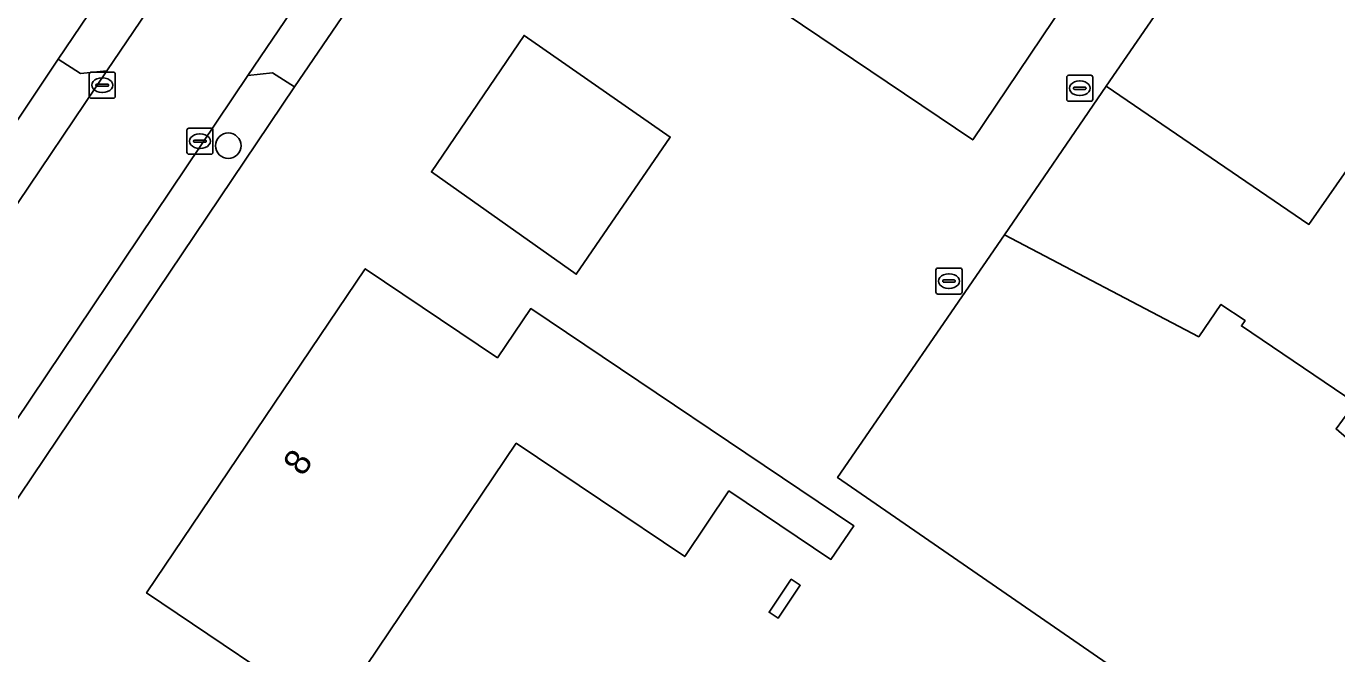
# Model space of a CAD drawing. Extents: x 163859 to 164644, y 379566 to 382155.
# Drawn here: x 164174.8 to 164225.1, y 381807.4 to 381831.6 of the extents above; entities that cross this region are included whole.
import ezdxf

# ---------------------------------------------------------------- set-up
doc = ezdxf.new("R2010")
doc.units = 0
for name, color, linetype in [('IMGEO_Boom', 7, 'Continuous'), ('IMGEO_Erf', 7, 'Continuous'), ('IMGEO_Kolk', 7, 'Continuous'), ('IMGEO_Muur', 7, 'Continuous'), ('IMGEO_Pand', 7, 'Continuous'), ('IMGEO_Pand_nummerreeks', 7, 'Continuous'), ('IMGEO_Rijbaan_lokaal_open', 7, 'Continuous'), ('IMGEO_Voetpad_halfverhard', 7, 'Continuous')]:
    doc.layers.add(name, color=color, linetype=linetype)

msp = doc.modelspace()

# ---------------------------------------------------------------- linework, layer by layer
at = {"layer": 'IMGEO_Boom'}
msp.add_circle((164182.545, 381826.968), 0.489, dxfattribs=at)
at = {"layer": 'IMGEO_Erf'}
for points in [[(164172.905, 381825.67), (164176.013, 381830.292), (164180.059, 381836.297), (164181.855, 381838.961), (164183.999, 381842.144), (164184.705, 381843.191), (164191.306, 381852.987), (164191.32, 381853.008), (164191.58, 381853.421), (164189.365, 381854.902), (164179.829, 381861.277), (164174.878, 381856.933)], [(164235.043, 381794.138), (164205.955, 381814.209), (164212.364, 381823.54), (164216.274, 381829.253), (164219.843, 381834.466), (164216.141, 381836.213), (164213.566, 381838.056), (164211.492, 381839.541), (164211.311, 381839.272), (164210.023, 381840.13), (164210.234, 381840.441), (164208.977, 381841.341), (164200.437, 381847.454), (164198.212, 381849.047), (164197.859, 381848.521), (164188.424, 381834.578), (164188.626, 381834.431), (164188.179, 381833.768), (164185.088, 381829.228), (164165.885, 381800.687)], [(164287.783, 381790.232), (164256.006, 381812.389), (164255.882, 381812.656), (164254.893, 381811.01), (164254.142, 381811.525), (164232.273, 381826.526), (164232.842, 381827.338), (164225.998, 381831.919), (164222.08, 381834.543), (164222.298, 381834.862), (164220.66, 381835.65), (164219.843, 381834.466), (164216.274, 381829.253), (164224.066, 381823.939), (164225.891, 381826.571), (164230.279, 381823.603), (164230.417, 381823.852)], [(164232.439, 381822.106), (164231.909, 381821.33), (164235.808, 381818.657), (164230.696, 381811.217), (164225.107, 381816.082), (164225.837, 381817.086), (164221.471, 381820.037), (164221.61, 381820.246), (164220.683, 381820.865), (164219.83, 381819.623), (164212.364, 381823.54), (164205.955, 381814.209), (164235.043, 381794.138), (164235.285, 381793.932), (164235.601, 381793.483), (164234.237, 381791.715), (164240.69, 381784.76), (164245.37, 381788.308), (164248.754, 381793.758), (164252.441, 381799.696), (164251.999, 381799.981), (164253.852, 381802.608)]]:
    msp.add_lwpolyline(points, dxfattribs=at)
for points in [[(164197.39, 381836.467), (164201.794, 381843.035), (164208.819, 381838.297), (164215.56, 381833.752), (164211.149, 381827.193)], [(164190.351, 381825.963), (164193.911, 381831.206), (164199.528, 381827.3), (164195.916, 381822.029)], [(164179.403, 381809.776), (164187.804, 381822.239), (164192.882, 381818.816), (164194.165, 381820.708), (164206.574, 381812.36), (164205.701, 381811.062), (164201.779, 381813.699), (164200.08, 381811.174), (164193.606, 381815.529), (164186.515, 381804.988)], [(164204.176, 381810.303), (164204.52, 381810.071), (164203.666, 381808.802), (164203.322, 381809.033)]]:
    msp.add_lwpolyline(points, close=True, dxfattribs=at)
at = {"layer": 'IMGEO_Kolk'}
for p, q in [((164177.203, 381828.869), (164177.203, 381829.721)), ((164177.278, 381829.795), (164178.13, 381829.795)), ((164178.204, 381829.721), (164178.204, 381828.869)), ((164214.759, 381828.751), (164214.759, 381829.603)), ((164214.834, 381829.677), (164215.686, 381829.677)), ((164215.76, 381829.603), (164215.76, 381828.751)), ((164177.462, 381829.289), (164177.462, 381829.301)), ((164177.9, 381829.252), (164177.502, 381829.252)), ((164177.505, 381829.338), (164177.903, 381829.338)), ((164177.691, 381829.575), (164177.716, 381829.575)), ((164177.946, 381829.301), (164177.946, 381829.289)), ((164215.018, 381829.171), (164215.018, 381829.183)), ((164215.456, 381829.134), (164215.058, 381829.134)), ((164215.061, 381829.22), (164215.459, 381829.22)), ((164215.247, 381829.457), (164215.272, 381829.457)), ((164215.502, 381829.183), (164215.502, 381829.171)), ((164178.13, 381828.795), (164177.278, 381828.795)), ((164177.714, 381829.015), (164177.689, 381829.015)), ((164215.686, 381828.677), (164214.834, 381828.677)), ((164215.27, 381828.897), (164215.245, 381828.897)), ((164181.029, 381827.641), (164181.881, 381827.641)), ((164180.954, 381826.715), (164180.954, 381827.567)), ((164181.213, 381827.135), (164181.213, 381827.147)), ((164181.651, 381827.098), (164181.253, 381827.098)), ((164181.256, 381827.184), (164181.654, 381827.184)), ((164181.442, 381827.421), (164181.467, 381827.421)), ((164181.697, 381827.147), (164181.697, 381827.135)), ((164181.955, 381827.567), (164181.955, 381826.715)), ((164181.881, 381826.641), (164181.029, 381826.641)), ((164181.465, 381826.861), (164181.44, 381826.861)), ((164209.734, 381821.337), (164209.734, 381822.189)), ((164209.809, 381822.263), (164210.661, 381822.263)), ((164210.222, 381822.043), (164210.247, 381822.043)), ((164210.735, 381822.189), (164210.735, 381821.337)), ((164209.993, 381821.757), (164209.993, 381821.769)), ((164210.431, 381821.72), (164210.033, 381821.72)), ((164210.036, 381821.806), (164210.434, 381821.806)), ((164210.477, 381821.769), (164210.477, 381821.757)), ((164210.661, 381821.263), (164209.809, 381821.263)), ((164210.245, 381821.483), (164210.22, 381821.483))]:
    msp.add_line(p, q, dxfattribs=at)
for points in [[(164177.203, 381828.869), (164177.203, 381829.721)], [(164177.278, 381829.795), (164178.13, 381829.795)], [(164178.204, 381829.721), (164178.204, 381828.869)], [(164214.759, 381828.751), (164214.759, 381829.603)], [(164214.834, 381829.677), (164215.686, 381829.677)], [(164215.76, 381829.603), (164215.76, 381828.751)], [(164178.13, 381828.795), (164177.278, 381828.795)], [(164215.686, 381828.677), (164214.834, 381828.677)], [(164181.029, 381827.641), (164181.881, 381827.641)], [(164180.954, 381826.715), (164180.954, 381827.567)], [(164181.955, 381827.567), (164181.955, 381826.715)], [(164181.881, 381826.641), (164181.029, 381826.641)], [(164209.734, 381821.337), (164209.734, 381822.189)], [(164209.809, 381822.263), (164210.661, 381822.263)], [(164210.735, 381822.189), (164210.735, 381821.337)], [(164210.661, 381821.263), (164209.809, 381821.263)]]:
    msp.add_lwpolyline(points, dxfattribs=at)
for centre, radius, start, end in [((164177.28, 381829.719), 0.0765, 91.552, 178.448), ((164177.28, 381829.719), 0.0765, 91.552, 178.448), ((164178.128, 381829.719), 0.0765, 1.552, 88.448), ((164178.128, 381829.719), 0.0765, 1.552, 88.448), ((164214.836, 381829.601), 0.0765, 91.552, 178.448), ((164214.836, 381829.601), 0.0765, 91.552, 178.448), ((164215.684, 381829.601), 0.0765, 1.552, 88.448), ((164215.684, 381829.601), 0.0765, 1.552, 88.448), ((164177.502, 381829.298), 0.0403, 85.8775, 175.7526), ((164177.499, 381829.288), 0.0366, 178.938, 274.7102), ((164177.903, 381829.295), 0.043, 264.8664, 352.4533), ((164177.907, 381829.3), 0.0386, 1.7309, 96.639), ((164215.058, 381829.18), 0.0403, 85.8775, 175.7526), ((164215.055, 381829.17), 0.0366, 178.938, 274.7102), ((164215.459, 381829.177), 0.043, 264.8664, 352.4533), ((164215.463, 381829.182), 0.0386, 1.7309, 96.639), ((164177.28, 381828.871), 0.0765, 181.552, 268.448), ((164177.28, 381828.871), 0.0765, 181.552, 268.448), ((164178.128, 381828.871), 0.0765, 271.552, 358.448), ((164178.128, 381828.871), 0.0765, 271.552, 358.448), ((164214.836, 381828.753), 0.0765, 181.552, 268.448), ((164214.836, 381828.753), 0.0765, 181.552, 268.448), ((164215.684, 381828.753), 0.0765, 271.552, 358.448), ((164215.684, 381828.753), 0.0765, 271.552, 358.448), ((164181.031, 381827.565), 0.0765, 91.552, 178.448), ((164181.031, 381827.565), 0.0765, 91.552, 178.448), ((164181.879, 381827.565), 0.0765, 1.552, 88.448), ((164181.879, 381827.565), 0.0765, 1.552, 88.448), ((164181.253, 381827.144), 0.0403, 85.8775, 175.7526), ((164181.25, 381827.134), 0.0366, 178.938, 274.7102), ((164181.654, 381827.141), 0.043, 264.8664, 352.4533), ((164181.658, 381827.146), 0.0386, 1.7309, 96.639), ((164181.031, 381826.717), 0.0765, 181.552, 268.448), ((164181.031, 381826.717), 0.0765, 181.552, 268.448), ((164181.879, 381826.717), 0.0765, 271.552, 358.448), ((164181.879, 381826.717), 0.0765, 271.552, 358.448), ((164209.811, 381822.187), 0.0765, 91.552, 178.448), ((164209.811, 381822.187), 0.0765, 91.552, 178.448), ((164210.659, 381822.187), 0.0765, 1.552, 88.448), ((164210.659, 381822.187), 0.0765, 1.552, 88.448), ((164210.033, 381821.766), 0.0403, 85.8775, 175.7526), ((164210.03, 381821.756), 0.0366, 178.938, 274.7102), ((164210.434, 381821.763), 0.043, 264.8664, 352.4533), ((164210.438, 381821.768), 0.0386, 1.7309, 96.639), ((164209.811, 381821.339), 0.0765, 181.552, 268.448), ((164209.811, 381821.339), 0.0765, 181.552, 268.448), ((164210.659, 381821.339), 0.0765, 271.552, 358.448), ((164210.659, 381821.339), 0.0765, 271.552, 358.448)]:
    msp.add_arc(centre, radius, start, end, dxfattribs=at)
for centre, major_axis, ratio, start_param, end_param in [((164177.69, 381829.295), (-0.387, 0.002), 0.722429, 4.712389, 7.853982), ((164177.715, 381829.295), (-0.39, 0.002), 0.717154, 1.570796, 4.712389), ((164215.246, 381829.177), (-0.387, 0.002), 0.722429, 4.712389, 7.853982), ((164215.271, 381829.177), (-0.39, 0.002), 0.717154, 1.570796, 4.712389), ((164181.441, 381827.141), (-0.387, 0.002), 0.722429, 4.712389, 7.853982), ((164181.466, 381827.141), (-0.39, 0.002), 0.717154, 1.570796, 4.712389), ((164210.221, 381821.763), (-0.387, 0.002), 0.722429, 4.712389, 7.853982), ((164210.246, 381821.763), (-0.39, 0.002), 0.717154, 1.570796, 4.712389)]:
    msp.add_ellipse(centre, major_axis=major_axis, ratio=ratio, start_param=start_param, end_param=end_param, dxfattribs=at)
at = {"layer": 'IMGEO_Muur'}
for points in [[(164216.274, 381829.253), (164219.843, 381834.466)], [(164235.043, 381794.138), (164205.955, 381814.209), (164212.364, 381823.54)]]:
    msp.add_lwpolyline(points, dxfattribs=at)
at = {"layer": 'IMGEO_Pand'}
for points in [[(164201.794, 381843.035), (164197.39, 381836.467), (164211.149, 381827.193), (164215.56, 381833.752), (164208.819, 381838.297)], [(164199.528, 381827.3), (164193.911, 381831.206), (164190.351, 381825.963), (164195.916, 381822.029)], [(164200.08, 381811.174), (164201.779, 381813.699), (164205.701, 381811.062), (164206.574, 381812.36), (164194.165, 381820.708), (164192.882, 381818.816), (164187.804, 381822.239), (164179.403, 381809.776), (164186.515, 381804.988), (164193.606, 381815.529)], [(164204.52, 381810.071), (164204.176, 381810.303), (164203.322, 381809.033), (164203.666, 381808.802)]]:
    msp.add_lwpolyline(points, close=True, dxfattribs=at)
msp.add_lwpolyline([(164230.417, 381823.852), (164230.279, 381823.603), (164225.891, 381826.571), (164224.066, 381823.939), (164216.274, 381829.253), (164212.364, 381823.54), (164219.83, 381819.623), (164220.683, 381820.865), (164221.61, 381820.246), (164221.471, 381820.037), (164225.837, 381817.086), (164225.107, 381816.082), (164230.696, 381811.217), (164235.808, 381818.657), (164231.909, 381821.33), (164232.439, 381822.106)], dxfattribs=at)
at = {"layer": 'IMGEO_Rijbaan_lokaal_open'}
for points in [[(164194.609, 381854.612), (164194.104, 381853.864), (164192.817, 381851.959), (164186.204, 381842.193), (164185.505, 381841.141), (164183.67, 381838.426), (164181.218, 381834.798), (164177.875, 381829.852), (164174.051, 381824.163), (164172.275, 381821.514), (164171.541, 381820.495), (164165.146, 381810.963), (164168.994, 381808.366), (164183.294, 381829.671)], [(164183.294, 381829.671), (164187.087, 381835.261), (164196.592, 381849.406), (164197.871, 381851.272), (164198.396, 381852.037)]]:
    msp.add_lwpolyline(points, dxfattribs=at)
for points in [[(164188.179, 381833.768), (164187.373, 381834.333), (164187.087, 381835.261), (164183.294, 381829.671), (164184.248, 381829.772), (164185.088, 381829.228)], [(164177.875, 381829.852), (164176.867, 381829.747), (164176.013, 381830.292), (164172.905, 381825.67), (164173.716, 381825.119), (164174.051, 381824.163)]]:
    msp.add_lwpolyline(points, close=True, dxfattribs=at)
at = {"layer": 'IMGEO_Voetpad_halfverhard'}
for points in [[(164181.218, 381834.798), (164180.897, 381835.736), (164180.059, 381836.297), (164176.013, 381830.292), (164176.867, 381829.747), (164177.875, 381829.852)], [(164185.088, 381829.228), (164184.248, 381829.772), (164183.294, 381829.671), (164168.994, 381808.366), (164167.007, 381805.504), (164164.432, 381801.664), (164165.885, 381800.687)]]:
    msp.add_lwpolyline(points, close=True, dxfattribs=at)

# ---------------------------------------------------------------- texts
at = {"layer": 'IMGEO_Pand_nummerreeks'}
msp.add_text('8', height=1, rotation=56.0181, dxfattribs=at).set_placement((164185.413, 381814.22))

doc.saveas('drawing.dxf')
